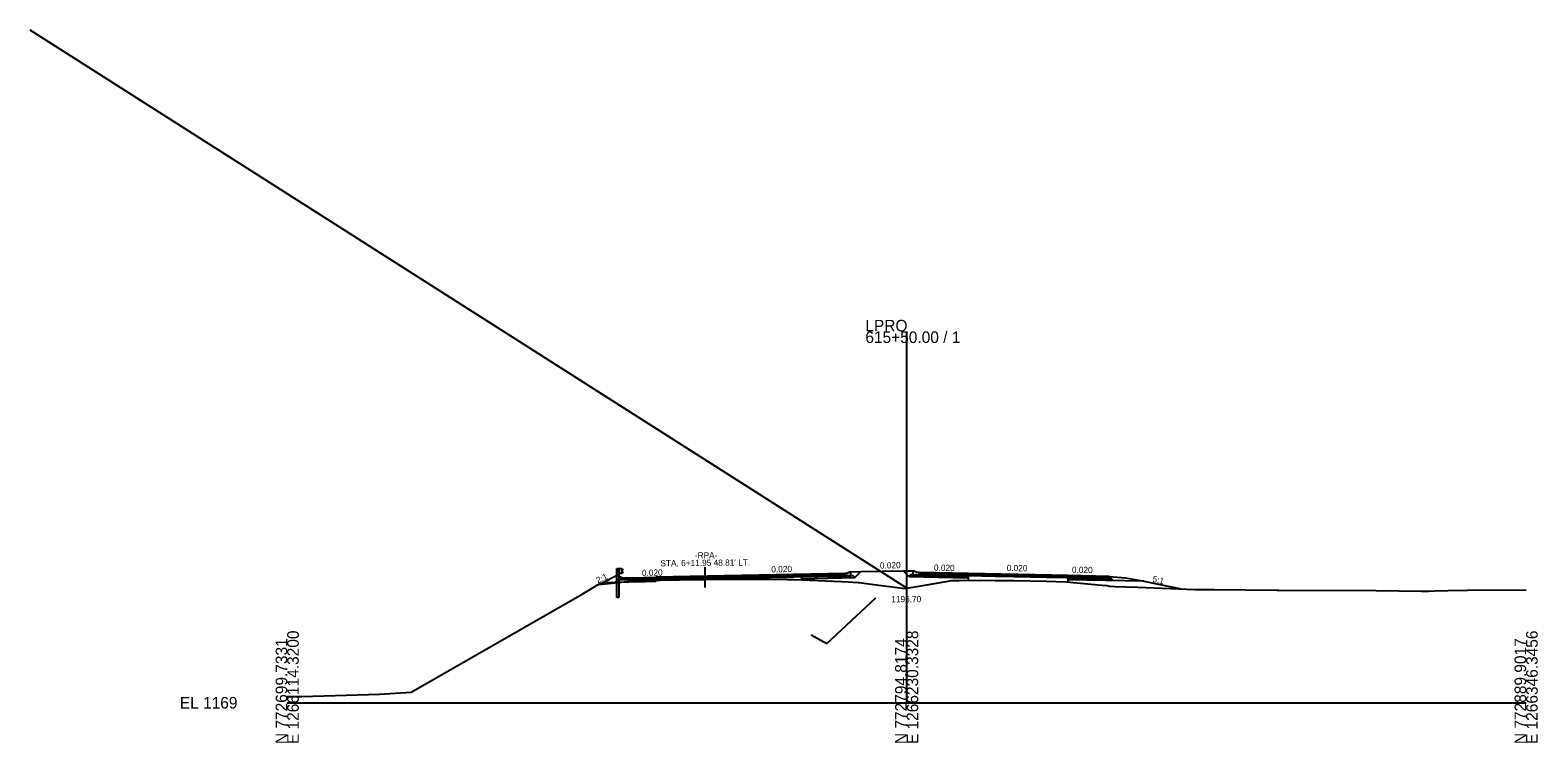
# Model space of a CAD drawing. Extents: x -3833 to 1267678, y -522 to 773248.
# Drawn here: x 1937.8 to 2302.8, y 6490.3 to 6662.8 of the extents above; entities that cross this region are included whole.
import ezdxf

# ---------------------------------------------------------------- set-up
doc = ezdxf.new("R2010")
doc.units = 0
for name, color, linetype in [('Exist Cross Section Cell', 7, 'Continuous'), ('Exist XS Center Line Elevation Label', 7, 'Continuous'), ('Exist XS Ground Line', 7, 'Continuous'), ('Prop CMT DNC', 7, 'Continuous'), ('Prop CMT Guardrail Graphics', 7, 'Continuous'), ('Prop CMT Pvmt Course 1', 7, 'Continuous'), ('Prop CMT Pvmt Course 2', 7, 'Continuous'), ('Prop CMT Pvmt Course 3', 7, 'Continuous'), ('Prop CMT Pvmt Course 4', 7, 'Continuous'), ('Prop CMT Shld Paved Course 1', 7, 'Continuous'), ('Prop CMT Shld Paved Course 2', 7, 'Continuous'), ('Prop CMT Shld Paved Course 4', 7, 'Continuous'), ('Prop CMT Slope Grass', 7, 'Continuous'), ('Prop CMT Subgrade Earthwork', 7, 'Continuous'), ('Prop Conc Curb and Gutter', 7, 'Continuous'), ('Prop Conc Island Cover', 7, 'Continuous'), ('Prop Corridor Mesh Bottom', 7, 'Continuous'), ('Prop XS Ditch Slope Text', 7, 'Continuous'), ('Prop XS Finish Grade', 7, 'Continuous'), ('Prop XS SE Text', 7, 'Continuous'), ('Prop XS Shear Point Element', 7, 'Continuous'), ('Scratch_Level_1', 7, 'Continuous'), ('Scratch_Level_5', 7, 'Continuous'), ('Typical Curb CELL', 7, 'Continuous')]:
    doc.layers.add(name, color=color, linetype=linetype)

msp = doc.modelspace()

# ---------------------------------------------------------------- linework, layer by layer
at = {"layer": 'Exist Cross Section Cell'}
for p, q in [((2150, 6500), (2150, 6589.86)), ((2000, 6500), (2150, 6500)), ((2150, 6500), (2300, 6500))]:
    msp.add_line(p, q, dxfattribs=at)
at = {"layer": 'Exist XS Ground Line'}
for p, q in [((2071.46, 6526.28), (2075.3, 6528.59)), ((2075.3, 6528.59), (2076.27, 6528.7)), ((2076.27, 6528.7), (2083.11, 6529.42)), ((2083.11, 6529.42), (2084.73, 6529.5)), ((2084.73, 6529.5), (2085.51, 6529.56)), ((2085.51, 6529.56), (2099.75, 6529.79)), ((2099.75, 6529.79), (2100.14, 6529.8)), ((2100.14, 6529.8), (2101.28, 6529.82)), ((2101.28, 6529.82), (2107.26, 6529.91)), ((2107.26, 6529.91), (2110.51, 6529.95)), ((2110.51, 6529.95), (2121.1, 6529.86)), ((2121.1, 6529.86), (2122.7, 6529.84)), ((2122.7, 6529.84), (2134.19, 6529.36)), ((2134.19, 6529.36), (2135.85, 6529.29)), ((2135.85, 6529.29), (2138.25, 6529.12)), ((2138.25, 6529.12), (2138.55, 6529.08)), ((2138.55, 6529.08), (2139.08, 6529)), ((2139.08, 6529), (2143.22, 6528.46)), ((2143.22, 6528.46), (2149.62, 6527.63)), ((2150, 6527.7), (2153.88, 6528.36)), ((2153.88, 6528.36), (2160.06, 6529.42)), ((2160.06, 6529.42), (2160.4, 6529.49)), ((2160.4, 6529.49), (2160.77, 6529.57)), ((2160.77, 6529.57), (2162.68, 6529.62)), ((2162.68, 6529.62), (2164.02, 6529.65)), ((2164.02, 6529.65), (2171.39, 6529.6)), ((2171.39, 6529.6), (2176.02, 6529.57)), ((2176.02, 6529.57), (2183.87, 6529.4)), ((2183.87, 6529.4), (2188.63, 6529.29)), ((2188.63, 6529.29), (2197.28, 6528.48)), ((2197.28, 6528.48), (2198.44, 6528.39)), ((2198.44, 6528.39), (2199.08, 6528.23)), ((2199.08, 6528.23), (2200.45, 6528.17)), ((2200.45, 6528.17), (2205.98, 6527.96)), ((2205.98, 6527.96), (2219.74, 6527.37)), ((2029.98, 6502.59), (2071.46, 6526.28)), ((2149.62, 6527.63), (2150, 6527.7)), ((2219.74, 6527.37), (2224.35, 6527.38)), ((2224.35, 6527.38), (2239.67, 6527.25)), ((2239.67, 6527.25), (2240.12, 6527.25)), ((2240.12, 6527.25), (2263.68, 6527.2)), ((2263.68, 6527.2), (2274.67, 6527.03)), ((2274.67, 6527.03), (2276.06, 6527.03)), ((2276.06, 6527.03), (2276.36, 6527.02)), ((2276.36, 6527.02), (2277.9, 6527.09)), ((2277.9, 6527.09), (2281.06, 6527.16)), ((2281.06, 6527.16), (2285.84, 6527.25)), ((2285.84, 6527.25), (2300, 6527.29)), ((2022.34, 6502.1), (2029.98, 6502.59)), ((2000, 6501.49), (2000.64, 6501.52)), ((2000.64, 6501.52), (2003.55, 6501.49)), ((2003.55, 6501.49), (2022.34, 6502.1))]:
    msp.add_line(p, q, dxfattribs=at)
at = {"layer": 'Prop CMT Guardrail Graphics'}
for p, q in [((2079.85, 6529.97), (2079.85, 6532.47)), ((2079.85, 6532.47), (2080.34, 6532.47)), ((2080.34, 6532.47), (2081, 6532.47)), ((2080.34, 6531.29), (2080.34, 6532.47)), ((2080.34, 6532.47), (2080.34, 6529.96)), ((2081, 6532.47), (2081, 6531.29)), ((2081, 6532.39), (2081.1, 6532.37)), ((2081, 6531.37), (2081, 6532.39)), ((2081, 6532.39), (2081, 6532.39)), ((2081, 6532.39), (2081, 6532.39)), ((2081.24, 6532.13), (2081.02, 6531.92)), ((2081.02, 6531.92), (2081.02, 6531.83)), ((2081.02, 6531.89), (2081.02, 6531.89)), ((2081.02, 6531.83), (2081.24, 6531.63)), ((2081.02, 6531.8), (2081.02, 6531.8)), ((2081.1, 6532.37), (2081.1, 6532.37)), ((2081.1, 6532.37), (2081.24, 6532.27)), ((2081.24, 6531.49), (2081.1, 6531.39)), ((2081.24, 6532.27), (2081.24, 6532.27)), ((2081.24, 6532.27), (2081.24, 6532.13)), ((2081.24, 6532.13), (2081.24, 6532.13)), ((2081.24, 6531.63), (2081.24, 6531.49)), ((2081.24, 6531.6), (2081.24, 6531.6)), ((2081.24, 6531.45), (2081.24, 6531.45)), ((2079.85, 6525.46), (2079.85, 6529.97)), ((2081, 6531.29), (2080.34, 6531.29)), ((2080.34, 6529.96), (2080.34, 6525.46)), ((2081.1, 6531.39), (2081, 6531.37)), ((2081.1, 6531.35), (2081.1, 6531.35)), ((2080.34, 6525.46), (2079.85, 6525.46))]:
    msp.add_line(p, q, dxfattribs=at)
at = {"layer": 'Prop CMT Pvmt Course 1'}
for p, q in [((2135, 6531.27), (2089.27, 6530.36)), ((2089.27, 6530.11), (2135, 6531.02)), ((2089.27, 6530.11), (2111, 6530.54)), ((2089.27, 6530.36), (2089.27, 6530.36)), ((2089.27, 6530.36), (2089.27, 6530.11)), ((2089.27, 6530.11), (2089.27, 6530.11)), ((2135, 6531.02), (2135, 6531.27)), ((2135, 6531.02), (2135, 6531.02)), ((2189, 6530.79), (2165, 6531.27)), ((2165, 6531.27), (2165, 6531.02)), ((2165, 6531.02), (2165, 6531.02)), ((2165, 6531.02), (2189, 6530.54)), ((2189, 6530.54), (2189, 6530.79)), ((2189, 6530.79), (2189, 6530.79)), ((2189, 6530.54), (2189, 6530.54)), ((2189, 6530.54), (2189, 6530.54))]:
    msp.add_line(p, q, dxfattribs=at)
at = {"layer": 'Prop CMT Pvmt Course 2'}
for p, q in [((2135, 6531.02), (2135, 6531.02)), ((2135, 6531.02), (2135, 6530.69)), ((2135, 6530.69), (2135, 6530.69)), ((2135, 6530.69), (2135, 6530.69)), ((2135, 6530.69), (2135, 6530.69)), ((2165, 6531.02), (2153, 6531.26)), ((2153, 6530.93), (2165, 6530.69)), ((2165, 6530.69), (2165, 6531.02)), ((2165, 6531.02), (2165, 6531.02)), ((2165, 6530.69), (2165, 6530.69)), ((2165, 6530.69), (2165, 6530.69)), ((2165, 6530.69), (2165, 6530.69))]:
    msp.add_line(p, q, dxfattribs=at)
at = {"layer": 'Prop CMT Pvmt Course 3'}
for p, q in [((2137.01, 6530.73), (2135, 6530.69)), ((2137.46, 6530.28), (2137.01, 6530.73)), ((2150.7, 6530.68), (2150.99, 6530.97)), ((2150.99, 6530.97), (2153, 6530.93))]:
    msp.add_line(p, q, dxfattribs=at)
at = {"layer": 'Prop CMT Pvmt Course 4'}
for p, q in [((2124.54, 6531.06), (2124.54, 6529.76)), ((2134, 6530.21), (2137.46, 6530.28)), ((2135, 6530.69), (2135, 6530.69)), ((2135, 6530.69), (2135, 6530.69)), ((2150.99, 6530.97), (2150.54, 6530.52)), ((2150.54, 6530.52), (2165, 6530.23)), ((2151.49, 6530.96), (2150.99, 6530.97)), ((2165, 6530.69), (2153, 6530.93)), ((2165, 6529.86), (2165, 6530.69)), ((2165, 6530.69), (2165, 6530.69)), ((2165, 6530.69), (2165, 6530.69)), ((2165, 6529.86), (2165, 6529.86)), ((2165, 6529.86), (2165, 6529.86)), ((2165, 6529.86), (2165, 6529.86))]:
    msp.add_line(p, q, dxfattribs=at)
at = {"layer": 'Prop CMT Shld Paved Course 1'}
for p, q in [((2165, 6531.27), (2153, 6531.51)), ((2081.01, 6529.91), (2081.01, 6529.91)), ((2081.01, 6529.91), (2081.01, 6529.91)), ((2081.01, 6529.91), (2081.01, 6529.91)), ((2081.01, 6529.91), (2081.01, 6529.91)), ((2081.27, 6530.16), (2081.27, 6530.16)), ((2081.27, 6530.16), (2081.27, 6530.16)), ((2083.6, 6530.25), (2089.27, 6530.36)), ((2089.27, 6530.11), (2085.02, 6530.02)), ((2089.27, 6530.36), (2089.27, 6530.11)), ((2135, 6531.27), (2135, 6531.27)), ((2135, 6531.27), (2135, 6531.02)), ((2135, 6531.02), (2135, 6531.02)), ((2135, 6531.02), (2135, 6531.02)), ((2153, 6531.26), (2165, 6531.02)), ((2165, 6531.02), (2165, 6531.27)), ((2165, 6531.27), (2165, 6531.27)), ((2165, 6531.02), (2165, 6531.02)), ((2165, 6531.02), (2165, 6531.02)), ((2199, 6530.59), (2189, 6530.79)), ((2199.26, 6530.34), (2199, 6530.59))]:
    msp.add_line(p, q, dxfattribs=at)
at = {"layer": 'Prop CMT Shld Paved Course 2'}
for p, q in [((2080.67, 6529.57), (2080.67, 6529.57)), ((2080.67, 6529.57), (2080.67, 6529.57)), ((2080.67, 6529.57), (2080.67, 6529.57)), ((2080.67, 6529.57), (2080.67, 6529.57)), ((2081.01, 6529.91), (2081.01, 6529.91)), ((2081.01, 6529.91), (2081.01, 6529.91)), ((2083.6, 6530), (2089.27, 6530.11)), ((2089.27, 6529.78), (2083.6, 6529.66)), ((2121.1, 6530.75), (2089.27, 6530.11)), ((2089.27, 6529.78), (2121.1, 6530.41)), ((2089.27, 6530.11), (2089.27, 6530.11)), ((2089.27, 6530.11), (2089.27, 6529.78)), ((2089.27, 6530.11), (2089.27, 6529.78)), ((2089.27, 6529.78), (2089.27, 6529.78)), ((2089.27, 6529.78), (2089.27, 6529.78)), ((2122.7, 6530.78), (2121.1, 6530.75)), ((2121.1, 6530.75), (2121.1, 6530.75)), ((2121.1, 6530.41), (2122.7, 6530.44)), ((2121.1, 6530.41), (2121.1, 6530.41)), ((2134.19, 6531.01), (2122.7, 6530.78)), ((2122.7, 6530.78), (2122.7, 6530.78)), ((2122.7, 6530.44), (2134.19, 6530.67)), ((2122.7, 6530.44), (2122.7, 6530.44)), ((2135, 6531.02), (2134.19, 6531.01)), ((2134.19, 6531.01), (2134.19, 6531.01)), ((2134.19, 6530.67), (2135, 6530.69)), ((2134.19, 6530.67), (2134.19, 6530.67)), ((2135, 6530.69), (2135, 6531.02)), ((2135, 6530.69), (2135, 6530.69)), ((2165, 6530.69), (2165, 6531.02)), ((2165, 6531.02), (2171.39, 6530.9)), ((2171.39, 6530.56), (2165, 6530.69)), ((2165, 6530.69), (2165, 6530.69)), ((2171.39, 6530.9), (2171.39, 6530.9)), ((2171.39, 6530.9), (2176.02, 6530.8)), ((2176.02, 6530.47), (2171.39, 6530.56)), ((2171.39, 6530.56), (2171.39, 6530.56)), ((2176.02, 6530.8), (2176.02, 6530.8)), ((2176.02, 6530.8), (2183.87, 6530.65)), ((2183.87, 6530.31), (2176.02, 6530.47)), ((2176.02, 6530.47), (2176.02, 6530.47)), ((2183.87, 6530.65), (2183.87, 6530.65)), ((2183.87, 6530.65), (2188.63, 6530.55)), ((2188.63, 6530.22), (2183.87, 6530.31)), ((2183.87, 6530.31), (2183.87, 6530.31)), ((2188.63, 6530.55), (2188.63, 6530.55)), ((2188.63, 6530.55), (2189, 6530.54)), ((2189, 6530.21), (2188.63, 6530.22)), ((2188.63, 6530.22), (2188.63, 6530.22)), ((2189, 6530.54), (2189, 6530.54)), ((2189, 6530.54), (2189, 6529.76)), ((2199.26, 6530.34), (2189, 6530.54)), ((2189, 6530.21), (2189, 6530.21)), ((2189, 6530.21), (2189, 6530.21)), ((2189, 6530.21), (2199.59, 6530)), ((2199.59, 6530), (2199.26, 6530.34))]:
    msp.add_line(p, q, dxfattribs=at)
at = {"layer": 'Prop CMT Shld Paved Course 4'}
for p, q in [((2079.37, 6529.12), (2080.07, 6529.83)), ((2080.07, 6529.83), (2080.58, 6529.83)), ((2083.6, 6529.83), (2083.6, 6529.67)), ((2089.27, 6529.32), (2084.21, 6529.22)), ((2084.68, 6529.68), (2085.18, 6529.69)), ((2085.18, 6529.69), (2089.27, 6529.78)), ((2089.27, 6529.78), (2089.27, 6529.32)), ((2200.06, 6529.53), (2199.59, 6530))]:
    msp.add_line(p, q, dxfattribs=at)
at = {"layer": 'Prop CMT Slope Grass'}
for p, q in [((2136.51, 6531.71), (2138.92, 6531.74)), ((2149.16, 6531.91), (2151.49, 6531.95)), ((2076.29, 6529.06), (2079.89, 6530.85)), ((2079.89, 6530.85), (2080.58, 6530.51)), ((2199, 6530.59), (2203, 6530.27)), ((2203, 6530.27), (2207.43, 6529.39))]:
    msp.add_line(p, q, dxfattribs=at)
at = {"layer": 'Prop CMT Subgrade Earthwork'}
for p, q in [((2137.46, 6530.28), (2138.92, 6531.74)), ((2150.54, 6530.52), (2149.16, 6531.91)), ((2089.27, 6529.32), (2076.29, 6529.06)), ((2089.27, 6529.32), (2089.27, 6529.62)), ((2124.54, 6530.02), (2137.46, 6530.28)), ((2124.54, 6529.76), (2124.54, 6530.02)), ((2165, 6530.23), (2150.54, 6530.52)), ((2165, 6529.64), (2165, 6530.23)), ((2207.43, 6529.39), (2189, 6529.76)), ((2189, 6529.76), (2189, 6529.26))]:
    msp.add_line(p, q, dxfattribs=at)
at = {"layer": 'Prop Conc Curb and Gutter'}
for p, q in [((2136.51, 6531.71), (2135.75, 6531.46)), ((2135.75, 6531.46), (2135.75, 6531.46)), ((2135.75, 6531.46), (2135.75, 6531.29)), ((2136.51, 6530.72), (2136.51, 6531.71)), ((2152.25, 6531.7), (2151.49, 6531.95)), ((2151.49, 6531.95), (2151.49, 6530.96)), ((2152.25, 6531.53), (2152.25, 6531.7)), ((2152.25, 6531.7), (2152.25, 6531.7)), ((2153, 6531.51), (2152.25, 6531.53)), ((2152.25, 6531.53), (2152.25, 6531.53)), ((2153, 6530.93), (2153, 6531.51)), ((2153, 6531.51), (2153, 6531.51)), ((2135.75, 6531.29), (2135, 6531.27)), ((2135, 6531.27), (2135, 6531.27)), ((2135, 6531.27), (2135, 6530.69)), ((2135, 6530.69), (2136.51, 6530.72)), ((2135, 6530.69), (2135, 6530.69)), ((2135, 6530.69), (2135, 6530.69)), ((2135.75, 6531.29), (2135.75, 6531.29)), ((2136.51, 6530.72), (2136.51, 6530.72)), ((2151.49, 6530.96), (2151.49, 6530.96)), ((2151.49, 6530.96), (2153, 6530.93)), ((2153, 6530.93), (2153, 6530.93)), ((2153, 6530.93), (2153, 6530.93))]:
    msp.add_line(p, q, dxfattribs=at)
at = {"layer": 'Prop Conc Island Cover'}
for p, q in [((2136.51, 6531.46), (2136.51, 6531.71)), ((2151.49, 6531.95), (2151.49, 6531.95)), ((2151.49, 6531.7), (2151.49, 6531.7))]:
    msp.add_line(p, q, dxfattribs=at)
at = {"layer": 'Prop Corridor Mesh Bottom'}
for p, q in [((2135, 6531.27), (2135, 6531.02)), ((2165, 6531.27), (2165, 6531.02)), ((2189, 6530.79), (2189, 6530.54))]:
    msp.add_line(p, q, dxfattribs=at)
at = {"layer": 'Prop XS Finish Grade'}
for p, q in [((2138.92, 6531.74), (2149.16, 6531.91)), ((2075.38, 6528.6), (2076.29, 6529.06)), ((2077.24, 6529.6), (2077.24, 6529.6)), ((2077.24, 6529.6), (2077.24, 6529.6)), ((2207.43, 6529.39), (2216.91, 6527.49))]:
    msp.add_line(p, q, dxfattribs=at)
at = {"layer": 'Prop XS Shear Point Element'}
msp.add_line((2101.19, 6527.89), (2101.19, 6532.78), dxfattribs=at)
at = {"layer": 'Scratch_Level_1'}
msp.add_line((2150, 6527.7), (1937.75, 6662.76), dxfattribs=at)
at = {"layer": 'Scratch_Level_5'}
for p, q in [((2130.66, 6514.34), (2142.52, 6525.36)), ((2126.88, 6516.44), (2130.66, 6514.34))]:
    msp.add_line(p, q, dxfattribs=at)
at = {"layer": 'Typical Curb CELL'}
for p, q in [((2080.58, 6529.83), (2080.58, 6530.51)), ((2081.27, 6530.16), (2080.58, 6530.51)), ((2080.58, 6529.83), (2083.6, 6529.83)), ((2080.62, 6530.13), (2080.77, 6530.17)), ((2080.76, 6530.08), (2080.62, 6530.13)), ((2080.77, 6530.17), (2080.76, 6530.08)), ((2081.29, 6530.04), (2081.19, 6529.97)), ((2081.19, 6529.97), (2081.35, 6529.93)), ((2083.59, 6530.25), (2081.27, 6530.16)), ((2081.35, 6529.93), (2081.29, 6530.04)), ((2082.03, 6530.1), (2082, 6529.99)), ((2082, 6529.99), (2082.12, 6529.98)), ((2082.12, 6529.98), (2082.03, 6530.1)), ((2082.54, 6530.04), (2082.43, 6529.97)), ((2082.43, 6529.97), (2082.6, 6529.93)), ((2082.6, 6529.93), (2082.54, 6530.04)), ((2083.28, 6530.1), (2083.24, 6529.99)), ((2083.24, 6529.99), (2083.36, 6529.98)), ((2083.36, 6529.98), (2083.28, 6530.1)), ((2083.6, 6530.25), (2083.6, 6530.25)), ((2083.6, 6529.83), (2083.6, 6530.24))]:
    msp.add_line(p, q, dxfattribs=at)
for centre in [(2080.65, 6530.21), (2080.74, 6529.94), (2080.86, 6529.99), (2081.12, 6530.02), (2081.14, 6529.97), (2081.31, 6529.88), (2081.34, 6529.99), (2081.54, 6529.95), (2081.58, 6530.06), (2081.71, 6530.03), (2081.74, 6529.91), (2081.8, 6529.94), (2081.99, 6529.94), (2082.11, 6529.99), (2082.21, 6529.98), (2082.3, 6529.94), (2082.36, 6530.08), (2082.37, 6530.02), (2082.39, 6529.97), (2082.59, 6529.99), (2082.79, 6529.95), (2082.83, 6530.06), (2082.88, 6530.03), (2082.96, 6530.03), (2082.99, 6529.91), (2083.05, 6529.94), (2083.11, 6530.12), (2083.47, 6530.19), (2083.51, 6530.07)]:
    msp.add_circle(centre, 0.00802, dxfattribs=at)
msp.add_arc((2083.59, 6530.24), 0.0104, 0, 92.048, dxfattribs=at)

# ---------------------------------------------------------------- texts
at = {"layer": 'Exist Cross Section Cell'}
for s, p in [('615+50.00 / 1', (2140, 6587.06)), ('LPRO', (2140, 6589.86)), ('EL 1169', (1974, 6498.6))]:
    msp.add_text(s, height=2.8, dxfattribs=at).set_placement(p)
for s, p in [('E 1266114.3200', (2002.8, 6490)), ('E 1266230.3328', (2152.8, 6490)), ('E 1266346.3456', (2302.8, 6490)), ('N 772699.7331', (2000, 6490)), ('N 772794.8174', (2150, 6490)), ('N 772889.9017', (2300, 6490))]:
    msp.add_text(s, height=2.8, rotation=90, dxfattribs=at).set_placement(p)
at = {"layer": 'Exist XS Center Line Elevation Label'}
msp.add_text('1196.70', height=1.5, dxfattribs=at).set_placement((2146.27, 6524.34))
at = {"layer": 'Prop CMT DNC'}
for p in [(2152.25, 6531.53), (2111, 6530.79), (2135, 6531.27), (2135, 6531.27), (2135.75, 6531.29), (2165, 6531.27), (2165, 6531.27), (2189, 6530.79), (2189, 6530.79), (2199, 6530.59)]:
    msp.add_text('X', height=0.00025, dxfattribs=at).set_placement(p)
at = {"layer": 'Prop XS Ditch Slope Text'}
for s, rotation, p in [('2:1', 26.0231, (2075.24, 6528.83)), ('5:1', 348.7683, (2209.43, 6529.26))]:
    msp.add_text(s, height=1.5, rotation=rotation, dxfattribs=at).set_placement(p)
at = {"layer": 'Prop XS SE Text'}
for s, rotation, p in [('-RPA-', 0.5826, (2098.71, 6534.91)), ('0.020', 1.397, (2085.91, 6530.67)), ("STA. 6+11.95 48.81' LT.", 0.5826, (2090.38, 6533)), ('0.020', 1.397, (2117.24, 6531.53)), ('0.020', 1.299, (2143.54, 6532.46)), ('0.020', 358.8542, (2156.59, 6531.97)), ('0.020', 358.8542, (2174.22, 6531.9)), ('0.020', 358.8542, (2190, 6531.47))]:
    msp.add_text(s, height=1.5, rotation=rotation, dxfattribs=at).set_placement(p)

doc.saveas('drawing.dxf')
